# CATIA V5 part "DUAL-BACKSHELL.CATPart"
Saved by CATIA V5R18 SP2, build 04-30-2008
Part number: DUAL-BACKSHELL
Revision: ---
Publications: "Logical Termination.1", "BaCP", "Face_generated(BaCP)", "Axis_generated(BaCP)", "Face_generated(BaCP).1", "EHISUPPORT-RefPoint1", "EHISUPPORT-RefPlane1.1", "EHISUPPORT-RefPlane2", "EHISUPPORT-RefBasePlane.1", "EHISUPPORT-RefPoint2", "EHISUPPORT-RefPlane1.2", "EHISUPPORT-RefBasePlane.2", "BCP", "BaCPRPoint_generated(BCP)", "BaCPCPlane_generated(BCP)"
Bounding box of the stored display mesh (mm): x 0 to 36.195, y -45.695 to 45.695, z -9.258 to 9.258
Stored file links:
  C:\Users\ajc8720\Documents\BOEING_WORK\0001-2CES\004-AP242\Boeing-Generic_Harness_R3\DUAL-BACKSHELL.CATPart
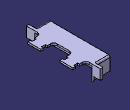
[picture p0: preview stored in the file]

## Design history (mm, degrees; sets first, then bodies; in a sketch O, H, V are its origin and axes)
Parameters
  PartNumber = "BACC10LD1"
  OverallBodyWidth = 91.3892 mm
  OverallBodyLength = 36.195 mm
  OverallBodyHeight = 18.5166 mm
  CenterHoleWidth = 9.9822 mm
  FrontBodyInnerWidth = 70.4088 mm
  FrontBodyWidth = 75.4888 mm
  FrontBodyLength = 20.193 mm
  CollarWidth = 16.002 mm
  CollarHeight = 3.2004 mm
  NeckWidth = 11.5062 mm
  InsideDraftWidth = 28.3972 mm
  InsideDraftHeight = 13.8938 mm
  NeckHeight = 4.8006 mm
  MoutingEarWidth = 10.541 mm
  MountingEarHeight = 12.446 mm
  MountingEarLength = 3.2004 mm
  FrontTopBodyLength = 6.096 mm
  ShoulderCurve = 4.191 mm
  CenterHoleHeight = 12.9794 mm
  InsertCornerRadius = 1.5494 mm
  CollarCenterSpacing = 39.5986 mm
  CollarThickness = 2.286 mm
  ShoulderWidth = 3.2004 mm
  CenterHoleRadius = 9.9822 mm
  CherbourgPlacement = 1.27 mm
  P_Part_1 = "A-A-59163-1II0040-1.000"
  P_Name_1 = "Tape"
  P_Qty_1 = "As required"
  P_Part_2 = "BACS38W1"
  P_Name_2 = "Plastic Tie Strap"
  P_Qty_2 = "As required"
  P_Part_3 = "Loctite222"
  P_Name_3 = "Adhesive"
  P_Qty_3 = "As required"
  `Strain Relief Backshell Assembly` = "http://www.boeing.com/product_standards/tps2?part=\"BACC10LD1\"&suop=\"Strain+Relief+Backshell+Assembly\""
Set1 "EGFOBody"
  Set2 "BCPOBody"
    Plane1 "BCPPlane": type Offset, RefPlane yz-plane, Offset 28.194 {= OverallBodyLength - CollarHeight - NeckHeight}
    Point1 "BCPRPoint": type OnPlane, Support Plane1, H 0, V 0, Direction (0, 1, 0)
  Set3 "BaCPOBody"
    Point2 "BaCPRPoint": type OnPlane, Support start face of Pad1, H 0, V 0, Direction (0, -1, 0)
    Plane2 "BaCPCPlane": type OffsetPt, RefPlane yz-plane, RefPoint Point2
  Set4 "SPTOBody"
    Point3 "EntryPoint1": (36.195, 19.685, 0)
    Plane3 "EntryPlane1": type OffsetPt, RefPlane face of Pad2 from Sketch4.L6, RefPoint Point3
    Point4 "EntryPlane2": type OnPlane, Support face of Pad2 from Sketch4.L20, H -20.4928, V 1.4119, Direction (0, 1, 0)
    Point5 "ExitPoint1": (25.4, 19.685, 0)
    Plane4 "ExitPlane1": type OffsetPt, RefPlane face of Pocket1 from Sketch2.L4, RefPoint Point5
    Point6 "BasePoint1": (30.48, 19.685, 6.9723)
    Plane5 "BasePlane1": type OffsetPt, RefPlane face of Pad2, RefPoint Point6
    Point7 "BasePoint2": (30.48, -19.685, 6.9723)
    Plane6 "BasePlane2": type OffsetPt, RefPlane face of Pad2, RefPoint Point7
    Plane7: type Tangent, Support Plane3, RefPoint Point3
    Plane8: type Offset, RefPlane Plane4, Offset 0, reversed
    Plane9: type Tangent, Support Plane3, RefPoint Point4
    Plane10: type Tangent, Support Plane3, RefPoint Point3
    Plane11: type Offset, RefPlane Plane4, Offset 0, reversed
    Plane12: type Tangent, Support Plane3, RefPoint Point4
Body1 (main body)
  Sketch1 on yz-plane, origin (0, 0, 0), H (0, 1, 0), V (0, 0, 1)
    line L1 (37.7444, 9.2583) -> (37.7444, -9.2583)
    line L2 (37.7444, -9.2583) -> (-37.7444, -9.2583)
    line L3 (-37.7444, -9.2583) -> (-37.7444, 9.2583)
    line L4 (-37.7444, 9.2583) -> (37.7444, 9.2583)
    length L1 = 18.5166 {= OverallBodyHeight}
    length L4 = 75.4888 {= FrontBodyWidth}
    vertical: L1 V, L3 V
    horizontal: L2 H, L4 H
    equidistance: L1 L3 O, L2 L4 O
  Pad1: profile Sketch1, direction (1, 0, 0), length 20.193 {= FrontBodyLength}
  Sketch2 on face of Pad1 from Sketch1.L2, origin (0, 0, -9.2583), H (1, 0, 0), V (0, -1, 0)
    line L1 (6.096, 35.2044) -> (20.193, 35.2044)
    line L2 (20.193, 35.2044) -> (20.193, -35.2044)
    line L3 (20.193, -35.2044) -> (6.096, -35.2044)
    line L4 (6.096, -35.2044) -> (6.096, 35.2044)
    distance L2 L4 = 14.097 {= FrontBodyLength - FrontTopBodyLength}
    distance L1 L3 = 70.4088 {= FrontBodyInnerWidth}
    distance L3 H = 35.2044 {= FrontBodyInnerWidth / 2}
    distance V L4 = 6.096 {= FrontTopBodyLength}
    horizontal: L1 H, L3 H
    vertical: L2 V, L4 V
  Pocket1: profile Sketch2, direction (0, 0, 1), length 16.2306 {= OverallBodyHeight - CollarThickness}
  Sketch3 on yz-plane, origin (0, 0, 0), H (0, 1, 0), V (0, 0, 1)
    line L1 (9.3472, 6.9469) -> (32.6644, 6.9469)
    line L2 (35.2044, 4.4069) -> (35.2044, -4.4069)
    line L3 (32.6644, -6.9469) -> (9.3472, -6.9469)
    line L4 (6.8072, -4.4069) -> (6.8072, 4.4069)
    arc A1 centre (32.6644, 4.4069) radius 2.54 from (35.2044, 4.4069) to (32.6644, 6.9469) ccw
    point P1 (35.2044, 4.4069)
    point P2 (32.6644, 6.9469)
    arc A2 centre (9.3472, -4.4069) radius 2.54 from (6.8072, -4.4069) to (9.3472, -6.9469) ccw
    point P4 (6.8072, -4.4069)
    point P5 (9.3472, -6.9469)
    arc A3 centre (9.3472, 4.4069) radius 2.54 from (9.3472, 6.9469) to (6.8072, 4.4069) ccw
    point P7 (9.3472, 6.9469)
    point P8 (6.8072, 4.4069)
    arc A4 centre (32.6644, -4.4069) radius 2.54 from (35.2044, -4.4069) to (32.6644, -6.9469) cw
    point P10 (35.2044, -4.4069)
    point P11 (32.6644, -6.9469)
    point P13 (-32.6644, -6.9469)
    point P14 (-35.2044, -4.4069)
    arc A5 centre (-32.6644, -4.4069) radius 2.54 from (-35.2044, -4.4069) to (-32.6644, -6.9469) ccw
    point P16 (-35.2044, 4.4069)
    line L5 (-35.2044, 4.4069) -> (-35.2044, -4.4069)
    point P17 (-32.6644, 6.9469)
    arc A6 centre (-32.6644, 4.4069) radius 2.54 from (-35.2044, 4.4069) to (-32.6644, 6.9469) cw
    point P19 (-9.3472, 6.9469)
    line L6 (-9.3472, 6.9469) -> (-32.6644, 6.9469)
    point P20 (-6.8072, 4.4069)
    arc A7 centre (-9.3472, 4.4069) radius 2.54 from (-9.3472, 6.9469) to (-6.8072, 4.4069) cw
    point P22 (-6.8072, -4.4069)
    line L7 (-6.8072, -4.4069) -> (-6.8072, 4.4069)
    point P23 (-9.3472, -6.9469)
    arc A8 centre (-9.3472, -4.4069) radius 2.54 from (-6.8072, -4.4069) to (-9.3472, -6.9469) cw
    line L8 (-32.6644, -6.9469) -> (-9.3472, -6.9469)
    point P25 (0, 9.1173)
    reference projected line E1 (35.2044, -9.2583) -> (35.2044, 6.9723) from edge [end face of Pad1 | face of Pocket1 from Sketch2.L3]
    radius A1 = 2.54
    radius A2 = 2.54 {= Sketch3.radius(A1)}
    radius A3 = 2.54 {= Sketch3.radius(A1)}
    radius A4 = 2.54 {= Sketch3.radius(A1)}
    distance L4 L2 = 28.3972 {= InsideDraftWidth}
    distance L1 L3 = 13.8938 {= InsideDraftHeight}
    distance L1 H = 6.9469 {= InsideDraftHeight /2}
    horizontal: L1 H, L3 H
    vertical: L2 V, L4 V
    tangency: A1 L2, A1 L1, A2 L4, A2 L3, A3 L1, A3 L4, A4 L2, A4 L3
    symmetry: P11 P13 V, P10 P14 V, A4 A5 V, P1 P16 V, L2 L5 V, P2 P17 V, A1 A6 V, P7 P19 V, L1 L6 V, P8 P20 V, A3 A7 V, P4 P22 V, L4 L7 V, P5 P23 V, A2 A8 V, L3 L8 V
    coincidence: P25 V, E1 L2
  Pocket2: profile Sketch3, direction (-1, 0, 0), length 14.097, mirrored extent
  Sketch4 on face of Pad1 from Sketch1.L4, origin (0, 0, 9.2583), H (1, 0, 0), V (0, 1, 0)
    line L1 (24.384, 27.8003) -> (28.194, 27.8003)
    point P1 (28.194, 27.8003)
    line L2 (28.194, 27.8003) -> (28.194, 25.5524)
    point P2 (28.194, 25.5524)
    line L3 (28.194, 25.5524) -> (32.9946, 25.5524)
    point P3 (32.9946, 25.5524)
    line L4 (32.9946, 25.5524) -> (32.9946, 27.8003)
    point P4 (32.9946, 27.8003)
    line L5 (32.9946, 27.8003) -> (36.195, 27.8003)
    point P5 (36.195, 27.8003)
    line L6 (36.195, 27.8003) -> (36.195, 11.7983)
    point P6 (36.195, 11.7983)
    line L7 (36.195, 11.7983) -> (32.9946, 11.7983)
    point P7 (32.9946, 11.7983)
    line L8 (32.9946, 11.7983) -> (32.9946, 14.0462)
    point P8 (32.9946, 14.0462)
    line L9 (32.9946, 14.0462) -> (28.194, 14.0462)
    point P9 (32.9946, 14.0462)
    point P10 (28.194, 14.0462)
    line L10 (28.194, 14.0462) -> (28.194, 11.7983)
    point P11 (28.194, 11.7983)
    line L11 (28.194, 11.7983) -> (24.384, 11.7983)
    point P12 (20.193, 7.6073)
    line L12 (20.193, 7.6073) -> (20.193, 7.6073)
    point P13 (14.097, -30.654)
    arc A1 centre (24.384, 31.9913) radius 4.191 from (24.384, 27.8003) to (20.193, 31.9913) cw
    point P14 (24.384, 27.8003)
    point P15 (20.193, 31.9913)
    arc A2 centre (24.384, 7.6073) radius 4.191 from (24.384, 11.7983) to (20.193, 7.6073) ccw
    point P17 (24.384, 11.7983)
    point P18 (20.193, 7.6073)
    line L13 (20.193, 31.9913) -> (20.193, 7.6073)
    point P20 (20.193, -7.6073)
    point P21 (20.193, -31.9913)
    line L14 (20.193, -31.9913) -> (20.193, -7.6073)
    point P22 (20.193, -7.6073)
    point P23 (24.384, -11.7983)
    arc A3 centre (24.384, -7.6073) radius 4.191 from (24.384, -11.7983) to (20.193, -7.6073) cw
    point P25 (28.194, -11.7983)
    line L15 (28.194, -11.7983) -> (24.384, -11.7983)
    point P26 (28.194, -14.0462)
    line L16 (28.194, -14.0462) -> (28.194, -11.7983)
    point P27 (32.9946, -14.0462)
    line L17 (32.9946, -14.0462) -> (28.194, -14.0462)
    point P28 (32.9946, -14.0462)
    point P29 (32.9946, -11.7983)
    line L18 (32.9946, -11.7983) -> (32.9946, -14.0462)
    point P30 (36.195, -11.7983)
    line L19 (36.195, -11.7983) -> (32.9946, -11.7983)
    point P31 (36.195, -27.8003)
    line L20 (36.195, -27.8003) -> (36.195, -11.7983)
    point P32 (32.9946, -27.8003)
    line L21 (32.9946, -27.8003) -> (36.195, -27.8003)
    point P33 (32.9946, -25.5524)
    line L22 (32.9946, -25.5524) -> (32.9946, -27.8003)
    point P34 (28.194, -25.5524)
    line L23 (28.194, -25.5524) -> (32.9946, -25.5524)
    point P35 (28.194, -27.8003)
    line L24 (28.194, -27.8003) -> (28.194, -25.5524)
    point P36 (24.384, -27.8003)
    line L25 (24.384, -27.8003) -> (28.194, -27.8003)
    arc A4 centre (24.384, -31.9913) radius 4.191 from (24.384, -27.8003) to (20.193, -31.9913) ccw
    distance L12 V = 20.193 {= FrontBodyLength}
    distance V L6 = 36.195 {= OverallBodyLength}
    radius A1 = 4.191 {= ShoulderCurve}
    distance L7 L5 = 16.002 {= CollarWidth}
    distance L3 L9 = 11.5062 {= NeckWidth}
    distance L11 H = 11.7983 {= (CollarCenterSpacing / 2) - (CollarWidth / 2)}
    radius A2 = 4.191 {= ShoulderCurve}
    distance L10 L8 = 4.8006 {= NeckHeight}
    distance L2 L4 = 4.8006 {= NeckHeight}
    distance L3 L5 = 2.2479 {= (CollarWidth  - NeckWidth ) / 2}
    distance L4 L6 = 3.2004 {= CollarHeight}
    horizontal: L1 H, L3 H, L5 H, L7 H, L9 H, L11 H
    coincidence: P4 L1, P11 L7, L4 L8, P9 P8, L12 P15, P18 P12
    vertical: L4 V, L6 V, L8 V, L10 V, L12 V, L2 V
    tangency: A1 L1, A1 L12, A2 L11, A2 L12, L13 A1
    symmetry: P12 P20 H, P15 P21 H, L13 L14 H, P18 P22 H, P17 P23 H, A2 A3 H, P11 P25 H, L11 L15 H, P10 P26 H, L10 L16 H, P9 P27 H, L9 L17 H, P8 P28 H, P7 P29 H, L8 L18 H, P6 P30 H, L7 L19 H, P5 P31 H, L6 L20 H, P4 P32 H, L5 L21 H, P3 P33 H, L4 L22 H, P2 P34 H, L3 L23 H, P1 P35 H, L2 L24 H, P14 P36 H, L1 L25 H, A1 A4 H
  Pad2 "tab.1": profile Sketch4, direction (0, 0, 1), length -2.286 {= -CollarThickness}
  Sketch5 on start face of Pad1, origin (0, 0, 0), H (0, -1, 0), V (0, 0, 1)
    line L1 (-4.9911, 5.1523) -> (-4.9911, -5.1523)
    line L2 (4.9911, 5.1523) -> (4.9911, -5.1523)
    arc A1 centre (0, -3.4925) radius 9.9822 from (4.9911, 5.1523) to (-4.9911, 5.1523) ccw
    point P1 (0, -3.4925)
    arc A2 centre (0, 3.4925) radius 9.9822 from (-4.9911, -5.1523) to (4.9911, -5.1523) ccw
    point P2 (0, 3.4925)
    radius A2 = 9.9822 {= CenterHoleRadius}
    distance L2 L1 = 9.9822 {= CenterHoleWidth}
    distance A1 A2 = 12.9794 {= CenterHoleHeight}
    vertical: L1 V, L2 V
    coincidence: P1 V, P2 V
    symmetry: L1 L2 V, A2 A1 H
  Pocket3: profile Sketch5, direction (1, 0, 0), length 6.096 {= FrontTopBodyLength}
  Sketch6 on end face of Pad1, origin (20.193, 0, 0), H (0, 1, 0), V (0, 0, 1)
    point P1 (37.7444, 9.2583)
    line L1 (37.7444, 9.2583) -> (45.6946, 9.2583)
    line L2 (45.6946, 9.2583) -> (45.6946, -3.1877)
    line L3 (45.6946, -3.1877) -> (37.7444, -3.1877)
    line L4 (37.7444, -3.1877) -> (37.7444, 9.2583)
    point P2 (45.6946, 9.2583)
    point P3 (45.6946, -3.1877)
    point P4 (37.7444, -3.1877)
    point P5 (-37.7444, -3.1877)
    point P6 (-45.6946, -3.1877)
    line L5 (-45.6946, -3.1877) -> (-37.7444, -3.1877)
    point P7 (-37.7444, 9.2583)
    line L6 (-37.7444, -3.1877) -> (-37.7444, 9.2583)
    point P8 (-45.6946, 9.2583)
    line L7 (-37.7444, 9.2583) -> (-45.6946, 9.2583)
    line L8 (-45.6946, 9.2583) -> (-45.6946, -3.1877)
    distance L4 V = 37.7444 {= FrontBodyWidth / 2}
    distance V L2 = 45.6946 {= OverallBodyWidth /2}
    distance L1 L3 = 12.446 {= MountingEarHeight}
    distance H L1 = 9.2583 {= OverallBodyHeight / 2}
    horizontal: L1 H, L3 H
    vertical: L2 V, L4 V
    symmetry: P4 P5 V, P3 P6 V, L3 L5 V, P1 P7 V, L4 L6 V, P2 P8 V, L1 L7 V, L2 L8 V
  Pad3: profile Sketch6, direction (1, 0, 0), length -3.2004 {= -MountingEarLength}
  Fillet1: radius 2.032, on edge [face of Pad1 from Sketch1.L3 | face of Pad3]; edge [face of Pad1 from Sketch1.L2 | face of Pad1 from Sketch1.L3]; edge [face of Pad1 from Sketch1.L1 | face of Pad1 from Sketch1.L2]; edge [face of Pad3 | face of Pad1 from Sketch1.L1]
Body2 "Male-CherbourgPartBody-BaCP"
  Sketch7 on Plane2, origin (0, 0, 0), H (0, 1, 0), V (0, 0, 1)
    arc A1 centre (0, 0) radius 1.016 from (-0.672, 0.762) to (0.672, 0.762) ccw
    line L1 (-0.672, 0.762) -> (0.672, 0.762)
    distance L1 H = 0.762
    radius A1 = 1.016
  Pad4: profile Sketch7, direction (1, 0, 0), length 0.508
Relations
  P_Part = P_Part_1
  P_Name = P_Name_1
  P_Qty = P_Qty_1
  P_Part = P_Part_2
  P_Name = P_Name_2
  P_Qty = P_Qty_2
  P_Part = P_Part_3
  P_Name = P_Name_3
  P_Qty = P_Qty_3
  URI_LINK = `Strain Relief Backshell Assembly`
